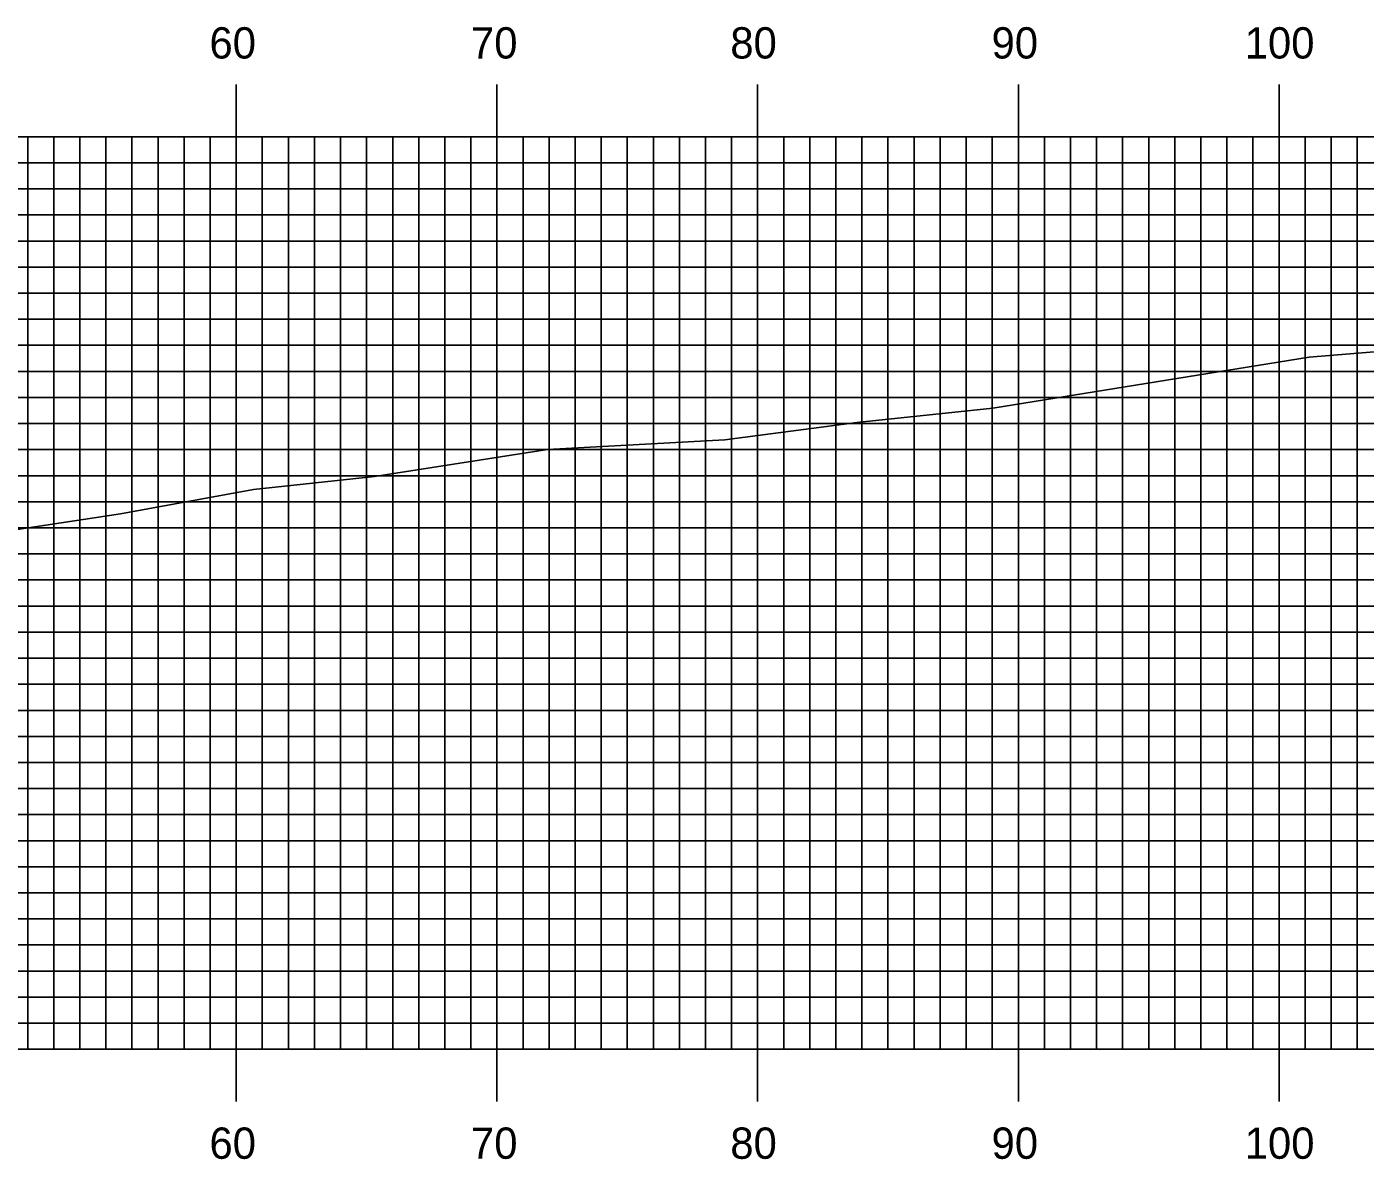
# Model space of a CAD drawing. Extents: x 1782254 to 1782597, y 442591 to 442811.
# Drawn here: x 1782471.4 to 1782522.7, y 442659.4 to 442702.9 of the extents above; entities that cross this region are included whole.
import ezdxf

# ---------------------------------------------------------------- set-up
doc = ezdxf.new("R2010")
doc.units = 0
for name, color, linetype in [('H_V ANNOTATION', 7, 'Continuous'), ('MAJOR', 7, 'Continuous'), ('MINOR', 7, 'Continuous'), ('S_Roadway_Centerline', 7, 'Continuous')]:
    doc.layers.add(name, color=color, linetype=linetype)

msp = doc.modelspace()

# ---------------------------------------------------------------- linework, layer by layer
at = {"layer": 'MAJOR'}
for p, q in [((1782479.434, 442700.669), (1782479.434, 442698.665)), ((1782489.434, 442700.669), (1782489.434, 442698.665)), ((1782499.434, 442700.669), (1782499.434, 442698.665)), ((1782509.434, 442700.669), (1782509.434, 442698.665)), ((1782519.434, 442700.669), (1782519.434, 442698.665)), ((1782279.434, 442698.665), (1782559.434, 442698.665)), ((1782279.434, 442698.665), (1782559.434, 442698.665)), ((1782479.434, 442663.665), (1782479.434, 442698.665)), ((1782489.434, 442663.665), (1782489.434, 442698.665)), ((1782499.434, 442663.665), (1782499.434, 442698.665)), ((1782509.434, 442663.665), (1782509.434, 442698.665)), ((1782519.434, 442663.665), (1782519.434, 442698.665)), ((1782279.434, 442693.665), (1782559.434, 442693.665)), ((1782279.434, 442688.665), (1782559.434, 442688.665)), ((1782279.434, 442683.665), (1782559.434, 442683.665)), ((1782279.434, 442678.665), (1782559.434, 442678.665)), ((1782279.434, 442673.665), (1782559.434, 442673.665)), ((1782279.434, 442668.665), (1782559.434, 442668.665)), ((1782279.434, 442663.665), (1782559.434, 442663.665)), ((1782279.434, 442663.665), (1782559.434, 442663.665)), ((1782479.434, 442661.661), (1782479.434, 442663.665)), ((1782489.434, 442661.661), (1782489.434, 442663.665)), ((1782499.434, 442661.661), (1782499.434, 442663.665)), ((1782509.434, 442661.661), (1782509.434, 442663.665)), ((1782519.434, 442661.661), (1782519.434, 442663.665))]:
    msp.add_line(p, q, dxfattribs=at)
at = {"layer": 'MINOR'}
for p, q in [((1782471.434, 442663.665), (1782471.434, 442698.665)), ((1782472.434, 442663.665), (1782472.434, 442698.665)), ((1782473.434, 442663.665), (1782473.434, 442698.665)), ((1782474.434, 442663.665), (1782474.434, 442698.665)), ((1782475.434, 442663.665), (1782475.434, 442698.665)), ((1782476.434, 442663.665), (1782476.434, 442698.665)), ((1782477.434, 442663.665), (1782477.434, 442698.665)), ((1782478.434, 442663.665), (1782478.434, 442698.665)), ((1782480.434, 442663.665), (1782480.434, 442698.665)), ((1782481.434, 442663.665), (1782481.434, 442698.665)), ((1782482.434, 442663.665), (1782482.434, 442698.665)), ((1782483.434, 442663.665), (1782483.434, 442698.665)), ((1782484.434, 442663.665), (1782484.434, 442698.665)), ((1782485.434, 442663.665), (1782485.434, 442698.665)), ((1782486.434, 442663.665), (1782486.434, 442698.665)), ((1782487.434, 442663.665), (1782487.434, 442698.665)), ((1782488.434, 442663.665), (1782488.434, 442698.665)), ((1782490.434, 442663.665), (1782490.434, 442698.665)), ((1782491.434, 442663.665), (1782491.434, 442698.665)), ((1782492.434, 442663.665), (1782492.434, 442698.665)), ((1782493.434, 442663.665), (1782493.434, 442698.665)), ((1782494.434, 442663.665), (1782494.434, 442698.665)), ((1782495.434, 442663.665), (1782495.434, 442698.665)), ((1782496.434, 442663.665), (1782496.434, 442698.665)), ((1782497.434, 442663.665), (1782497.434, 442698.665)), ((1782498.434, 442663.665), (1782498.434, 442698.665)), ((1782500.434, 442663.665), (1782500.434, 442698.665)), ((1782501.434, 442663.665), (1782501.434, 442698.665)), ((1782502.434, 442663.665), (1782502.434, 442698.665)), ((1782503.434, 442663.665), (1782503.434, 442698.665)), ((1782504.434, 442663.665), (1782504.434, 442698.665)), ((1782505.434, 442663.665), (1782505.434, 442698.665)), ((1782506.434, 442663.665), (1782506.434, 442698.665)), ((1782507.434, 442663.665), (1782507.434, 442698.665)), ((1782508.434, 442663.665), (1782508.434, 442698.665)), ((1782510.434, 442663.665), (1782510.434, 442698.665)), ((1782511.434, 442663.665), (1782511.434, 442698.665)), ((1782512.434, 442663.665), (1782512.434, 442698.665)), ((1782513.434, 442663.665), (1782513.434, 442698.665)), ((1782514.434, 442663.665), (1782514.434, 442698.665)), ((1782515.434, 442663.665), (1782515.434, 442698.665)), ((1782516.434, 442663.665), (1782516.434, 442698.665)), ((1782517.434, 442663.665), (1782517.434, 442698.665)), ((1782518.434, 442663.665), (1782518.434, 442698.665)), ((1782520.434, 442663.665), (1782520.434, 442698.665)), ((1782521.434, 442663.665), (1782521.434, 442698.665)), ((1782522.434, 442663.665), (1782522.434, 442698.665)), ((1782279.434, 442697.665), (1782559.434, 442697.665)), ((1782279.434, 442696.665), (1782559.434, 442696.665)), ((1782279.434, 442695.665), (1782559.434, 442695.665)), ((1782279.434, 442694.665), (1782559.434, 442694.665)), ((1782279.434, 442692.665), (1782559.434, 442692.665)), ((1782279.434, 442691.665), (1782559.434, 442691.665)), ((1782279.434, 442690.665), (1782559.434, 442690.665)), ((1782279.434, 442689.665), (1782559.434, 442689.665)), ((1782279.434, 442687.665), (1782559.434, 442687.665)), ((1782279.434, 442686.665), (1782559.434, 442686.665)), ((1782279.434, 442685.665), (1782559.434, 442685.665)), ((1782279.434, 442684.665), (1782559.434, 442684.665)), ((1782279.434, 442682.665), (1782559.434, 442682.665)), ((1782279.434, 442681.665), (1782559.434, 442681.665)), ((1782279.434, 442680.665), (1782559.434, 442680.665)), ((1782279.434, 442679.665), (1782559.434, 442679.665)), ((1782279.434, 442677.665), (1782559.434, 442677.665)), ((1782279.434, 442676.665), (1782559.434, 442676.665)), ((1782279.434, 442675.665), (1782559.434, 442675.665)), ((1782279.434, 442674.665), (1782559.434, 442674.665)), ((1782279.434, 442672.665), (1782559.434, 442672.665)), ((1782279.434, 442671.665), (1782559.434, 442671.665)), ((1782279.434, 442670.665), (1782559.434, 442670.665)), ((1782279.434, 442669.665), (1782559.434, 442669.665)), ((1782279.434, 442667.665), (1782559.434, 442667.665)), ((1782279.434, 442666.665), (1782559.434, 442666.665)), ((1782279.434, 442665.665), (1782559.434, 442665.665)), ((1782279.434, 442664.665), (1782559.434, 442664.665))]:
    msp.add_line(p, q, dxfattribs=at)
at = {"layer": 'S_Roadway_Centerline'}
msp.add_lwpolyline([(1782460.569, 442682.018), (1782474.99, 442684.196), (1782480.091, 442685.131), (1782484.737, 442685.638), (1782491.374, 442686.672), (1782498.173, 442687.041), (1782503.237, 442687.706), (1782508.456, 442688.254), (1782520.587, 442690.211), (1782533.23, 442691.244), (1782538.419, 442691.506), (1782543.376, 442691.608), (1782549.431, 442691.718), (1782559.434, 442692.574)], dxfattribs=at)

# ---------------------------------------------------------------- texts
at = {"layer": 'H_V ANNOTATION'}
for s, p in [('60', (1782478.406, 442701.665)), ('70', (1782488.438, 442701.665)), ('80', (1782498.385, 442701.665)), ('90', (1782508.406, 442701.665)), ('100', (1782518.117, 442701.665)), ('60', (1782478.406, 442659.465)), ('70', (1782488.438, 442659.465)), ('80', (1782498.385, 442659.465)), ('90', (1782508.406, 442659.465)), ('100', (1782518.117, 442659.465))]:
    msp.add_text(s, height=1.2, dxfattribs=at).set_placement(p)

doc.saveas('drawing.dxf')
